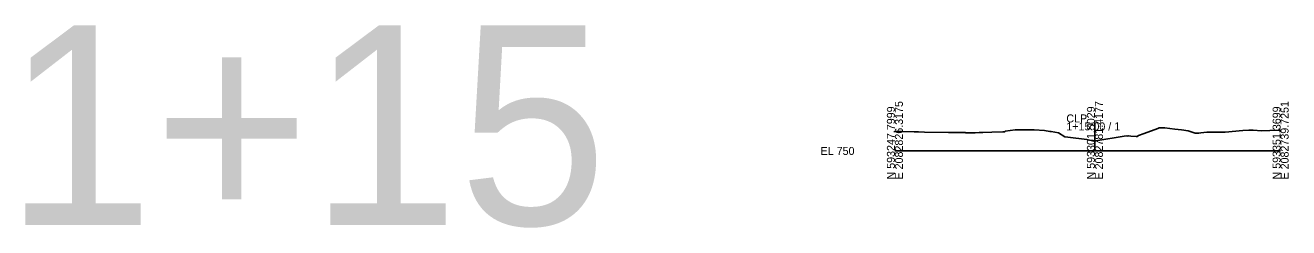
# Model space of a CAD drawing. Extents: x -577 to 1138, y -35 to 4556.
# Drawn here: x 695.6 to 1137.8, y 1473.1 to 1544.1 of the extents above; entities that cross this region are included whole.
import ezdxf

# ---------------------------------------------------------------- set-up
doc = ezdxf.new("R2010")
doc.units = 0
for name, color, linetype in [('GK_Cells', 7, 'Continuous'), ('SC_Scratch1', 7, 'Continuous'), ('XS_X_Ground_Line', 7, 'Continuous')]:
    doc.layers.add(name, color=color, linetype=linetype)

msp = doc.modelspace()

# ---------------------------------------------------------------- linework, layer by layer
at = {"layer": 'GK_Cells'}
for p, q in [((1070, 1500), (1070, 1510)), ((1000, 1500), (1070, 1500)), ((1070, 1500), (1135, 1500))]:
    msp.add_line(p, q, dxfattribs=at)
at = {"layer": 'XS_X_Ground_Line'}
for p, q in [((1091.97, 1507.88), (1092.55, 1508.1)), ((1092.55, 1508.1), (1094.53, 1508.09)), ((1094.53, 1508.09), (1097.94, 1507.67)), ((1000, 1506.8), (1002.42, 1506.76)), ((1002.42, 1506.76), (1006.79, 1506.69)), ((1006.79, 1506.69), (1008.21, 1506.67)), ((1008.21, 1506.67), (1010.35, 1506.63)), ((1010.35, 1506.63), (1018.81, 1506.49)), ((1018.81, 1506.49), (1021.5, 1506.45)), ((1021.5, 1506.45), (1022.34, 1506.44)), ((1022.34, 1506.44), (1024.55, 1506.41)), ((1024.55, 1506.41), (1024.79, 1506.4)), ((1024.79, 1506.4), (1027.49, 1506.35)), ((1027.49, 1506.35), (1028.12, 1506.34)), ((1028.12, 1506.34), (1029.48, 1506.45)), ((1029.48, 1506.45), (1030.72, 1506.5)), ((1030.72, 1506.5), (1033.96, 1506.64)), ((1033.96, 1506.64), (1037.74, 1506.7)), ((1037.74, 1506.7), (1038.45, 1506.73)), ((1038.45, 1506.73), (1038.58, 1506.88)), ((1038.58, 1506.88), (1042.04, 1507.38)), ((1042.04, 1507.38), (1048.79, 1507.44)), ((1048.79, 1507.44), (1052.37, 1507.22)), ((1052.37, 1507.22), (1054.21, 1506.79)), ((1054.21, 1506.79), (1054.75, 1506.8)), ((1054.75, 1506.8), (1057.25, 1506.34)), ((1057.25, 1506.34), (1059.44, 1505)), ((1059.44, 1505), (1060.49, 1504.81)), ((1060.49, 1504.81), (1060.5, 1504.81)), ((1060.5, 1504.81), (1067.18, 1504.04)), ((1067.18, 1504.04), (1067.21, 1504.04)), ((1067.21, 1504.04), (1069.63, 1503.43)), ((1069.63, 1503.43), (1080.93, 1505.24)), ((1080.93, 1505.24), (1081.41, 1505.2)), ((1081.41, 1505.2), (1081.56, 1505.25)), ((1081.56, 1505.25), (1081.73, 1505.29)), ((1081.73, 1505.29), (1082.62, 1505.17)), ((1082.62, 1505.17), (1084.46, 1505.05)), ((1084.46, 1505.05), (1084.79, 1505.07)), ((1084.79, 1505.07), (1085.31, 1505.44)), ((1085.31, 1505.44), (1087.23, 1506.14)), ((1087.23, 1506.14), (1091.97, 1507.88)), ((1097.94, 1507.67), (1100.31, 1507.38)), ((1100.31, 1507.38), (1102.61, 1507.09)), ((1102.61, 1507.09), (1105.11, 1506.2)), ((1105.11, 1506.2), (1106.37, 1506.27)), ((1106.37, 1506.27), (1107.05, 1506.36)), ((1107.05, 1506.36), (1109.14, 1506.61)), ((1109.14, 1506.61), (1114.09, 1506.57)), ((1114.09, 1506.57), (1115.65, 1506.63)), ((1115.65, 1506.63), (1121.75, 1507.12)), ((1121.75, 1507.12), (1123.87, 1507.24)), ((1123.87, 1507.24), (1124.01, 1507.24)), ((1124.01, 1507.24), (1125.41, 1507.29)), ((1125.41, 1507.29), (1128.29, 1507.1)), ((1128.29, 1507.1), (1134.17, 1507.23)), ((1134.17, 1507.23), (1135, 1507.3))]:
    msp.add_line(p, q, dxfattribs=at)

# ---------------------------------------------------------------- texts
at = {"layer": 'GK_Cells'}
for s, p in [('E 2082826.3175', (1002.8, 1490)), ('E 2082781.4177', (1072.8, 1490)), ('E 2082739.7251', (1137.8, 1490)), ('N 593247.7999', (1000, 1490)), ('N 593301.5029', (1070, 1490)), ('N 593351.3699', (1135, 1490))]:
    msp.add_text(s, height=2.8, rotation=90, dxfattribs=at).set_placement(p)
for s, p in [('CLP_', (1060, 1510)), ('1+15.00 / 1', (1060, 1507.2)), ('EL 750', (974, 1498.6))]:
    msp.add_text(s, height=2.8, dxfattribs=at).set_placement(p)
at = {"layer": 'SC_Scratch1'}
msp.add_text('1+15', height=70, dxfattribs=at).set_placement((688.5, 1474.07))

doc.saveas('drawing.dxf')
